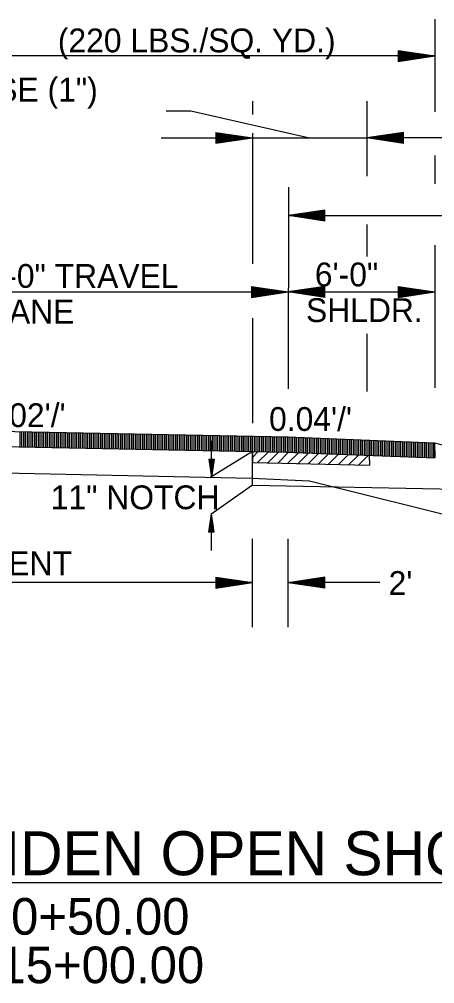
# Model space of a CAD drawing. Extents: x 1373719 to 1374161, y 379835 to 380167.
# Drawn here: x 1373788.32 to 1373799.66, y 380098.88 to 380125.22 of the extents above; entities that cross this region are included whole.
import ezdxf

# ---------------------------------------------------------------- set-up
doc = ezdxf.new("R2010")
doc.units = 0
for name, color, linetype in [('ACHM Surface', 7, 'Continuous'), ('Binder', 7, 'Continuous'), ('GREEN_TXT', 7, 'Continuous'), ('Pavement Layers', 7, 'Continuous'), ('T_Drafting', 7, 'Continuous')]:
    doc.layers.add(name, color=color, linetype=linetype)

msp = doc.modelspace()

# ---------------------------------------------------------------- linework, layer by layer
for p, q in [((1373784.662, 380114.03), (1373795.66, 380113.81)), ((1373795.66, 380113.81), (1373799.657, 380113.65)), ((1373799.657, 380113.65), (1373815.66, 380109.65)), ((1373794.689, 380112.496), (1373805.107, 380112.288))]:
    msp.add_line(p, q)
for points in [[(1373784.659, 380113.614), (1373794.689, 380113.413), (1373795.603, 380113.395), (1373797.747, 380113.31), (1373799.665, 380113.237)], [(1373794.689, 380112.496), (1373794.689, 380113.413)]]:
    msp.add_lwpolyline(points)
at = {"layer": 'ACHM Surface'}
for p, q in [((1373788.343, 380113.54), (1373788.343, 380113.957)), ((1373788.393, 380113.539), (1373788.393, 380113.956)), ((1373788.443, 380113.538), (1373788.443, 380113.955)), ((1373788.493, 380113.537), (1373788.493, 380113.954)), ((1373788.543, 380113.536), (1373788.543, 380113.953)), ((1373788.593, 380113.535), (1373788.593, 380113.952)), ((1373788.643, 380113.534), (1373788.643, 380113.951)), ((1373788.693, 380113.533), (1373788.693, 380113.95)), ((1373788.743, 380113.532), (1373788.743, 380113.949)), ((1373788.793, 380113.531), (1373788.793, 380113.948)), ((1373788.843, 380113.53), (1373788.843, 380113.947)), ((1373788.893, 380113.529), (1373788.893, 380113.946)), ((1373788.943, 380113.528), (1373788.943, 380113.945)), ((1373788.993, 380113.527), (1373788.993, 380113.944)), ((1373789.043, 380113.526), (1373789.043, 380113.943)), ((1373789.093, 380113.525), (1373789.093, 380113.942)), ((1373789.143, 380113.524), (1373789.143, 380113.941)), ((1373789.193, 380113.523), (1373789.193, 380113.94)), ((1373789.243, 380113.522), (1373789.243, 380113.939)), ((1373789.293, 380113.521), (1373789.293, 380113.938)), ((1373789.343, 380113.52), (1373789.343, 380113.937)), ((1373789.393, 380113.519), (1373789.393, 380113.936)), ((1373789.443, 380113.518), (1373789.443, 380113.935)), ((1373789.493, 380113.517), (1373789.493, 380113.934)), ((1373789.543, 380113.516), (1373789.543, 380113.933)), ((1373789.593, 380113.515), (1373789.593, 380113.932)), ((1373789.643, 380113.514), (1373789.643, 380113.931)), ((1373789.693, 380113.513), (1373789.693, 380113.93)), ((1373789.743, 380113.512), (1373789.743, 380113.929)), ((1373789.793, 380113.511), (1373789.793, 380113.928)), ((1373789.843, 380113.51), (1373789.843, 380113.927)), ((1373789.893, 380113.509), (1373789.893, 380113.926)), ((1373789.943, 380113.508), (1373789.943, 380113.925)), ((1373789.993, 380113.507), (1373789.993, 380113.924)), ((1373790.043, 380113.506), (1373790.043, 380113.923)), ((1373790.093, 380113.505), (1373790.093, 380113.922)), ((1373790.143, 380113.504), (1373790.143, 380113.921)), ((1373790.193, 380113.503), (1373790.193, 380113.92)), ((1373790.243, 380113.502), (1373790.243, 380113.919)), ((1373790.293, 380113.501), (1373790.293, 380113.918)), ((1373790.343, 380113.5), (1373790.343, 380113.917)), ((1373790.393, 380113.499), (1373790.393, 380113.916)), ((1373790.443, 380113.498), (1373790.443, 380113.915)), ((1373790.493, 380113.497), (1373790.493, 380113.914)), ((1373790.543, 380113.496), (1373790.543, 380113.913)), ((1373790.593, 380113.495), (1373790.593, 380113.912)), ((1373790.643, 380113.494), (1373790.643, 380113.911)), ((1373790.693, 380113.493), (1373790.693, 380113.91)), ((1373790.743, 380113.492), (1373790.743, 380113.909)), ((1373790.793, 380113.491), (1373790.793, 380113.908)), ((1373790.843, 380113.49), (1373790.843, 380113.907)), ((1373790.893, 380113.489), (1373790.893, 380113.906)), ((1373790.943, 380113.488), (1373790.943, 380113.905)), ((1373790.993, 380113.487), (1373790.993, 380113.904)), ((1373791.043, 380113.486), (1373791.043, 380113.903)), ((1373791.093, 380113.485), (1373791.093, 380113.902)), ((1373791.143, 380113.484), (1373791.143, 380113.901)), ((1373791.193, 380113.483), (1373791.193, 380113.9)), ((1373791.243, 380113.482), (1373791.243, 380113.899)), ((1373791.293, 380113.481), (1373791.293, 380113.898)), ((1373791.343, 380113.48), (1373791.343, 380113.897)), ((1373791.393, 380113.479), (1373791.393, 380113.896)), ((1373791.443, 380113.478), (1373791.443, 380113.895)), ((1373791.493, 380113.477), (1373791.493, 380113.894)), ((1373791.543, 380113.476), (1373791.543, 380113.893)), ((1373791.593, 380113.475), (1373791.593, 380113.892)), ((1373791.643, 380113.474), (1373791.643, 380113.891)), ((1373791.693, 380113.473), (1373791.693, 380113.89)), ((1373791.743, 380113.472), (1373791.743, 380113.889)), ((1373791.793, 380113.471), (1373791.793, 380113.888)), ((1373791.843, 380113.47), (1373791.843, 380113.887)), ((1373791.893, 380113.469), (1373791.893, 380113.886)), ((1373791.943, 380113.468), (1373791.943, 380113.885)), ((1373791.993, 380113.467), (1373791.993, 380113.884)), ((1373792.043, 380113.466), (1373792.043, 380113.883)), ((1373792.093, 380113.465), (1373792.093, 380113.882)), ((1373792.143, 380113.464), (1373792.143, 380113.881)), ((1373792.193, 380113.463), (1373792.193, 380113.88)), ((1373792.243, 380113.462), (1373792.243, 380113.879)), ((1373792.293, 380113.461), (1373792.293, 380113.878)), ((1373792.343, 380113.46), (1373792.343, 380113.877)), ((1373792.393, 380113.459), (1373792.393, 380113.876)), ((1373792.443, 380113.458), (1373792.443, 380113.875)), ((1373792.493, 380113.457), (1373792.493, 380113.874)), ((1373792.543, 380113.456), (1373792.543, 380113.873)), ((1373792.593, 380113.455), (1373792.593, 380113.872)), ((1373792.643, 380113.454), (1373792.643, 380113.871)), ((1373792.693, 380113.453), (1373792.693, 380113.87)), ((1373792.743, 380113.452), (1373792.743, 380113.869)), ((1373792.793, 380113.451), (1373792.793, 380113.868)), ((1373792.843, 380113.45), (1373792.843, 380113.867)), ((1373792.893, 380113.449), (1373792.893, 380113.866)), ((1373792.943, 380113.448), (1373792.943, 380113.865)), ((1373792.993, 380113.447), (1373792.993, 380113.864)), ((1373793.043, 380113.446), (1373793.043, 380113.863)), ((1373793.093, 380113.445), (1373793.093, 380113.862)), ((1373793.143, 380113.444), (1373793.143, 380113.861)), ((1373793.193, 380113.443), (1373793.193, 380113.86)), ((1373793.243, 380113.442), (1373793.243, 380113.859)), ((1373793.293, 380113.441), (1373793.293, 380113.858)), ((1373793.343, 380113.44), (1373793.343, 380113.857)), ((1373793.393, 380113.439), (1373793.393, 380113.856)), ((1373793.443, 380113.438), (1373793.443, 380113.855)), ((1373793.493, 380113.437), (1373793.493, 380113.854)), ((1373793.543, 380113.436), (1373793.543, 380113.853)), ((1373793.593, 380113.435), (1373793.593, 380113.852)), ((1373793.643, 380113.434), (1373793.643, 380113.851)), ((1373793.693, 380113.433), (1373793.693, 380113.85)), ((1373793.743, 380113.432), (1373793.743, 380113.849)), ((1373793.793, 380113.431), (1373793.793, 380113.848)), ((1373793.843, 380113.43), (1373793.843, 380113.847)), ((1373793.893, 380113.429), (1373793.893, 380113.846)), ((1373793.943, 380113.428), (1373793.943, 380113.845)), ((1373793.993, 380113.427), (1373793.993, 380113.844)), ((1373794.043, 380113.426), (1373794.043, 380113.843)), ((1373794.093, 380113.425), (1373794.093, 380113.842)), ((1373794.143, 380113.424), (1373794.143, 380113.841)), ((1373794.193, 380113.423), (1373794.193, 380113.84)), ((1373794.243, 380113.422), (1373794.243, 380113.839)), ((1373794.293, 380113.421), (1373794.293, 380113.838)), ((1373794.343, 380113.42), (1373794.343, 380113.837)), ((1373794.393, 380113.419), (1373794.393, 380113.836)), ((1373794.443, 380113.418), (1373794.443, 380113.835)), ((1373794.493, 380113.417), (1373794.493, 380113.834)), ((1373794.543, 380113.416), (1373794.543, 380113.833)), ((1373794.593, 380113.415), (1373794.593, 380113.832)), ((1373794.643, 380113.414), (1373794.643, 380113.831)), ((1373794.693, 380113.413), (1373794.693, 380113.83)), ((1373794.743, 380113.412), (1373794.743, 380113.829)), ((1373794.793, 380113.411), (1373794.793, 380113.828)), ((1373794.843, 380113.41), (1373794.843, 380113.827)), ((1373794.893, 380113.409), (1373794.893, 380113.826)), ((1373794.943, 380113.408), (1373794.943, 380113.825)), ((1373794.993, 380113.407), (1373794.993, 380113.824)), ((1373795.043, 380113.406), (1373795.043, 380113.823)), ((1373795.093, 380113.405), (1373795.093, 380113.822)), ((1373795.143, 380113.404), (1373795.143, 380113.821)), ((1373795.193, 380113.403), (1373795.193, 380113.82)), ((1373795.243, 380113.402), (1373795.243, 380113.819)), ((1373795.293, 380113.401), (1373795.293, 380113.818)), ((1373795.343, 380113.4), (1373795.343, 380113.817)), ((1373795.393, 380113.399), (1373795.393, 380113.816)), ((1373795.443, 380113.398), (1373795.443, 380113.815)), ((1373795.493, 380113.397), (1373795.493, 380113.814)), ((1373795.543, 380113.396), (1373795.543, 380113.813)), ((1373795.593, 380113.395), (1373795.593, 380113.812)), ((1373795.643, 380113.394), (1373795.643, 380113.811)), ((1373795.693, 380113.392), (1373795.693, 380113.809)), ((1373795.743, 380113.39), (1373795.743, 380113.807)), ((1373795.793, 380113.388), (1373795.793, 380113.805)), ((1373795.843, 380113.386), (1373795.843, 380113.803)), ((1373795.893, 380113.384), (1373795.893, 380113.801)), ((1373795.943, 380113.382), (1373795.943, 380113.799)), ((1373795.993, 380113.38), (1373795.993, 380113.797)), ((1373796.043, 380113.379), (1373796.043, 380113.795)), ((1373796.093, 380113.377), (1373796.093, 380113.793)), ((1373796.143, 380113.375), (1373796.143, 380113.791)), ((1373796.193, 380113.373), (1373796.193, 380113.789)), ((1373796.243, 380113.371), (1373796.243, 380113.787)), ((1373796.293, 380113.369), (1373796.293, 380113.785)), ((1373796.343, 380113.367), (1373796.343, 380113.783)), ((1373796.393, 380113.365), (1373796.393, 380113.781)), ((1373796.443, 380113.363), (1373796.443, 380113.779)), ((1373796.493, 380113.361), (1373796.493, 380113.777)), ((1373796.543, 380113.359), (1373796.543, 380113.775)), ((1373796.593, 380113.357), (1373796.593, 380113.773)), ((1373796.643, 380113.355), (1373796.643, 380113.771)), ((1373796.693, 380113.353), (1373796.693, 380113.769)), ((1373796.743, 380113.351), (1373796.743, 380113.767)), ((1373796.793, 380113.349), (1373796.793, 380113.765)), ((1373796.843, 380113.347), (1373796.843, 380113.763)), ((1373796.893, 380113.345), (1373796.893, 380113.761)), ((1373796.943, 380113.343), (1373796.943, 380113.759)), ((1373796.993, 380113.341), (1373796.993, 380113.757)), ((1373797.043, 380113.339), (1373797.043, 380113.755)), ((1373797.093, 380113.337), (1373797.093, 380113.753)), ((1373797.143, 380113.335), (1373797.143, 380113.751)), ((1373797.193, 380113.334), (1373797.193, 380113.749)), ((1373797.243, 380113.332), (1373797.243, 380113.747)), ((1373797.293, 380113.33), (1373797.293, 380113.745)), ((1373797.343, 380113.328), (1373797.343, 380113.743)), ((1373797.393, 380113.326), (1373797.393, 380113.741)), ((1373797.443, 380113.324), (1373797.443, 380113.739)), ((1373797.493, 380113.322), (1373797.493, 380113.737)), ((1373797.543, 380113.32), (1373797.543, 380113.735)), ((1373797.593, 380113.318), (1373797.593, 380113.733)), ((1373797.643, 380113.316), (1373797.643, 380113.731)), ((1373797.693, 380113.314), (1373797.693, 380113.729)), ((1373797.743, 380113.312), (1373797.743, 380113.727)), ((1373797.793, 380113.31), (1373797.793, 380113.725)), ((1373797.843, 380113.308), (1373797.843, 380113.723)), ((1373797.893, 380113.306), (1373797.893, 380113.721)), ((1373797.943, 380113.304), (1373797.943, 380113.719)), ((1373797.993, 380113.302), (1373797.993, 380113.717)), ((1373798.043, 380113.3), (1373798.043, 380113.715)), ((1373798.093, 380113.298), (1373798.093, 380113.713)), ((1373798.143, 380113.296), (1373798.143, 380113.711)), ((1373798.193, 380113.294), (1373798.193, 380113.709)), ((1373798.243, 380113.292), (1373798.243, 380113.707)), ((1373798.293, 380113.291), (1373798.293, 380113.705)), ((1373798.343, 380113.289), (1373798.343, 380113.703)), ((1373798.393, 380113.287), (1373798.393, 380113.701)), ((1373798.443, 380113.285), (1373798.443, 380113.699)), ((1373798.493, 380113.283), (1373798.493, 380113.697)), ((1373798.543, 380113.281), (1373798.543, 380113.695)), ((1373798.593, 380113.279), (1373798.593, 380113.693)), ((1373798.643, 380113.277), (1373798.643, 380113.691)), ((1373798.693, 380113.275), (1373798.693, 380113.689)), ((1373798.743, 380113.273), (1373798.743, 380113.687)), ((1373798.793, 380113.271), (1373798.793, 380113.685)), ((1373798.843, 380113.269), (1373798.843, 380113.683)), ((1373798.893, 380113.267), (1373798.893, 380113.681)), ((1373798.943, 380113.265), (1373798.943, 380113.679)), ((1373798.993, 380113.263), (1373798.993, 380113.677)), ((1373799.043, 380113.261), (1373799.043, 380113.675)), ((1373799.093, 380113.259), (1373799.093, 380113.673)), ((1373799.143, 380113.257), (1373799.143, 380113.671)), ((1373799.193, 380113.255), (1373799.193, 380113.669)), ((1373799.243, 380113.253), (1373799.243, 380113.667)), ((1373799.293, 380113.251), (1373799.293, 380113.665)), ((1373799.343, 380113.249), (1373799.343, 380113.663)), ((1373799.393, 380113.248), (1373799.393, 380113.661)), ((1373799.443, 380113.246), (1373799.443, 380113.659)), ((1373799.493, 380113.244), (1373799.493, 380113.657)), ((1373799.543, 380113.242), (1373799.543, 380113.655)), ((1373799.593, 380113.24), (1373799.593, 380113.653)), ((1373799.643, 380113.238), (1373799.643, 380113.651))]:
    msp.add_line(p, q, dxfattribs=at)
at = {"layer": 'Binder'}
for p, q in [((1373794.689, 380113.254), (1373794.844, 380113.41)), ((1373794.827, 380113.11), (1373795.122, 380113.404)), ((1373795.104, 380113.104), (1373795.399, 380113.399)), ((1373795.381, 380113.097), (1373795.675, 380113.392)), ((1373795.657, 380113.091), (1373795.947, 380113.381)), ((1373795.934, 380113.085), (1373796.219, 380113.371)), ((1373796.211, 380113.079), (1373796.492, 380113.36)), ((1373796.487, 380113.073), (1373796.764, 380113.349)), ((1373796.764, 380113.067), (1373797.036, 380113.338)), ((1373797.041, 380113.06), (1373797.308, 380113.327)), ((1373797.317, 380113.054), (1373797.58, 380113.317)), ((1373797.594, 380113.048), (1373797.852, 380113.306)), ((1373797.871, 380113.042), (1373797.881, 380113.052))]:
    msp.add_line(p, q, dxfattribs=at)
at = {"layer": 'GREEN_TXT'}
for p, q in [((1373799.665, 380125.217), (1373799.665, 380122.691)), ((1373799.665, 380124.217), (1373769.664, 380124.217)), ((1373798.665, 380124.367), (1373799.665, 380124.217)), ((1373798.665, 380124.367), (1373798.665, 380124.067)), ((1373798.665, 380124.342), (1373799.498, 380124.217)), ((1373798.665, 380124.317), (1373799.326, 380124.217)), ((1373798.665, 380124.292), (1373799.159, 380124.217)), ((1373798.665, 380124.266), (1373798.99, 380124.217)), ((1373798.665, 380124.241), (1373798.823, 380124.217)), ((1373798.665, 380124.067), (1373799.665, 380124.217)), ((1373798.665, 380124.168), (1373798.99, 380124.217)), ((1373798.665, 380124.118), (1373799.326, 380124.217)), ((1373798.665, 380124.092), (1373799.498, 380124.217)), ((1373798.665, 380124.143), (1373799.159, 380124.217)), ((1373798.665, 380124.194), (1373798.823, 380124.217)), ((1373794.689, 380122.98), (1373794.689, 380122.615)), ((1373797.808, 380122.98), (1373797.808, 380120.931)), ((1373793.689, 380122.13), (1373794.689, 380121.98)), ((1373793.689, 380122.13), (1373793.689, 380121.83)), ((1373793.689, 380122.105), (1373794.522, 380121.98)), ((1373794.689, 380122.11), (1373794.689, 380118.539)), ((1373798.812, 380122.128), (1373797.812, 380121.978)), ((1373798.812, 380121.828), (1373798.812, 380122.128)), ((1373792.193, 380121.98), (1373794.693, 380121.978)), ((1373793.689, 380122.08), (1373794.35, 380121.98)), ((1373793.689, 380122.055), (1373794.183, 380121.98)), ((1373793.689, 380122.029), (1373794.014, 380121.98)), ((1373793.689, 380122.004), (1373793.847, 380121.98)), ((1373793.689, 380121.83), (1373794.689, 380121.98)), ((1373793.689, 380121.931), (1373794.014, 380121.98)), ((1373793.689, 380121.881), (1373794.35, 380121.98)), ((1373793.689, 380121.855), (1373794.522, 380121.98)), ((1373793.689, 380121.906), (1373794.183, 380121.98)), ((1373793.689, 380121.957), (1373793.847, 380121.98)), ((1373794.689, 380121.98), (1373797.808, 380121.98)), ((1373800.308, 380121.98), (1373797.808, 380121.98)), ((1373798.812, 380121.828), (1373797.812, 380121.978)), ((1373798.812, 380122.103), (1373797.979, 380121.978)), ((1373798.812, 380121.853), (1373797.979, 380121.978)), ((1373798.812, 380122.077), (1373798.151, 380121.978)), ((1373798.812, 380121.878), (1373798.151, 380121.978)), ((1373798.812, 380122.052), (1373798.317, 380121.978)), ((1373798.812, 380121.903), (1373798.317, 380121.978)), ((1373798.812, 380122.027), (1373798.487, 380121.978)), ((1373798.812, 380121.929), (1373798.487, 380121.978)), ((1373798.812, 380122.001), (1373798.654, 380121.978)), ((1373798.812, 380121.954), (1373798.654, 380121.978)), ((1373799.665, 380121.501), (1373799.665, 380120.719)), ((1373795.668, 380120.628), (1373795.662, 380115.124)), ((1373796.668, 380120.005), (1373795.668, 380119.855)), ((1373796.668, 380119.705), (1373796.668, 380120.005)), ((1373795.668, 380119.855), (1373815.66, 380119.855)), ((1373796.668, 380119.705), (1373795.668, 380119.855)), ((1373796.668, 380119.98), (1373795.835, 380119.855)), ((1373796.668, 380119.73), (1373795.835, 380119.855)), ((1373796.668, 380119.954), (1373796.007, 380119.855)), ((1373796.668, 380119.755), (1373796.007, 380119.855)), ((1373796.668, 380119.929), (1373796.174, 380119.855)), ((1373796.668, 380119.78), (1373796.174, 380119.855)), ((1373796.668, 380119.904), (1373796.343, 380119.855)), ((1373796.668, 380119.806), (1373796.343, 380119.855)), ((1373796.668, 380119.878), (1373796.51, 380119.855)), ((1373796.668, 380119.831), (1373796.51, 380119.855)), ((1373797.808, 380119.609), (1373797.808, 380118.742)), ((1373799.665, 380119.048), (1373799.665, 380115.151)), ((1373794.665, 380117.922), (1373795.665, 380117.772)), ((1373794.665, 380117.922), (1373794.665, 380117.622)), ((1373794.665, 380117.897), (1373795.498, 380117.772)), ((1373796.665, 380117.922), (1373795.665, 380117.772)), ((1373796.665, 380117.897), (1373795.832, 380117.772)), ((1373796.665, 380117.622), (1373796.665, 380117.922)), ((1373798.665, 380117.922), (1373799.665, 380117.772)), ((1373798.665, 380117.922), (1373798.665, 380117.622)), ((1373798.665, 380117.897), (1373799.498, 380117.772)), ((1373773.664, 380117.772), (1373795.664, 380117.772)), ((1373794.665, 380117.871), (1373795.326, 380117.772)), ((1373794.665, 380117.846), (1373795.159, 380117.772)), ((1373794.665, 380117.82), (1373794.99, 380117.772)), ((1373794.665, 380117.795), (1373794.823, 380117.772)), ((1373794.665, 380117.622), (1373795.665, 380117.772)), ((1373794.665, 380117.723), (1373794.99, 380117.772)), ((1373794.665, 380117.672), (1373795.326, 380117.772)), ((1373794.665, 380117.647), (1373795.498, 380117.772)), ((1373794.665, 380117.697), (1373795.159, 380117.772)), ((1373794.665, 380117.748), (1373794.823, 380117.772)), ((1373795.665, 380117.772), (1373799.665, 380117.772)), ((1373796.665, 380117.622), (1373795.665, 380117.772)), ((1373796.665, 380117.647), (1373795.832, 380117.772)), ((1373796.665, 380117.871), (1373796.004, 380117.772)), ((1373796.665, 380117.672), (1373796.004, 380117.772)), ((1373796.665, 380117.846), (1373796.17, 380117.772)), ((1373796.665, 380117.697), (1373796.17, 380117.772)), ((1373796.665, 380117.821), (1373796.34, 380117.772)), ((1373796.665, 380117.723), (1373796.34, 380117.772)), ((1373796.665, 380117.795), (1373796.507, 380117.772)), ((1373796.665, 380117.748), (1373796.507, 380117.772)), ((1373798.665, 380117.871), (1373799.326, 380117.772)), ((1373798.665, 380117.846), (1373799.159, 380117.772)), ((1373798.665, 380117.82), (1373798.99, 380117.772)), ((1373798.665, 380117.795), (1373798.823, 380117.772)), ((1373798.665, 380117.622), (1373799.665, 380117.772)), ((1373798.665, 380117.723), (1373798.99, 380117.772)), ((1373798.665, 380117.672), (1373799.326, 380117.772)), ((1373798.665, 380117.647), (1373799.498, 380117.772)), ((1373798.665, 380117.697), (1373799.159, 380117.772)), ((1373798.665, 380117.748), (1373798.823, 380117.772)), ((1373794.689, 380117.055), (1373794.689, 380114.189)), ((1373797.808, 380116.625), (1373797.808, 380115.049)), ((1373793.567, 380112.708), (1373793.567, 380113.708)), ((1373794.686, 380113.414), (1373793.526, 380112.691)), ((1373793.492, 380113.208), (1373793.567, 380112.708)), ((1373793.492, 380113.208), (1373793.642, 380113.208)), ((1373793.505, 380113.208), (1373793.567, 380112.791)), ((1373793.518, 380113.208), (1373793.567, 380112.877)), ((1373793.53, 380113.208), (1373793.567, 380112.961)), ((1373793.543, 380113.208), (1373793.567, 380113.045)), ((1373793.556, 380113.208), (1373793.567, 380113.129)), ((1373793.642, 380113.208), (1373793.567, 380112.708)), ((1373793.592, 380113.208), (1373793.567, 380113.045)), ((1373793.617, 380113.208), (1373793.567, 380112.877)), ((1373793.63, 380113.208), (1373793.567, 380112.791)), ((1373793.605, 380113.208), (1373793.567, 380112.961)), ((1373793.579, 380113.208), (1373793.567, 380113.129)), ((1373794.686, 380112.497), (1373793.548, 380111.691)), ((1373793.492, 380111.21), (1373793.567, 380111.71)), ((1373793.505, 380111.21), (1373793.567, 380111.626)), ((1373793.567, 380110.71), (1373793.567, 380111.71)), ((1373793.642, 380111.21), (1373793.567, 380111.71)), ((1373793.63, 380111.21), (1373793.567, 380111.626)), ((1373793.518, 380111.21), (1373793.567, 380111.54)), ((1373793.53, 380111.21), (1373793.567, 380111.457)), ((1373793.543, 380111.21), (1373793.567, 380111.372)), ((1373793.617, 380111.21), (1373793.567, 380111.54)), ((1373793.605, 380111.21), (1373793.567, 380111.457)), ((1373793.592, 380111.21), (1373793.567, 380111.372)), ((1373793.642, 380111.21), (1373793.492, 380111.21)), ((1373793.556, 380111.21), (1373793.567, 380111.289)), ((1373793.579, 380111.21), (1373793.567, 380111.289)), ((1373794.689, 380109.832), (1373774.689, 380109.832)), ((1373793.689, 380109.982), (1373794.689, 380109.832)), ((1373793.689, 380109.982), (1373793.689, 380109.682)), ((1373793.689, 380109.957), (1373794.522, 380109.832)), ((1373793.689, 380109.932), (1373794.35, 380109.832)), ((1373793.689, 380109.907), (1373794.183, 380109.832)), ((1373793.689, 380109.881), (1373794.014, 380109.832)), ((1373793.689, 380109.856), (1373793.847, 380109.832)), ((1373793.689, 380109.682), (1373794.689, 380109.832)), ((1373793.689, 380109.783), (1373794.014, 380109.832)), ((1373793.689, 380109.733), (1373794.35, 380109.832)), ((1373793.689, 380109.707), (1373794.522, 380109.832)), ((1373793.689, 380109.758), (1373794.183, 380109.832)), ((1373793.689, 380109.809), (1373793.847, 380109.832)), ((1373798.162, 380109.832), (1373795.662, 380109.832)), ((1373796.665, 380109.98), (1373795.665, 380109.83)), ((1373796.665, 380109.68), (1373795.665, 380109.83)), ((1373796.665, 380109.955), (1373795.832, 380109.83)), ((1373796.665, 380109.705), (1373795.832, 380109.83)), ((1373796.665, 380109.93), (1373796.004, 380109.83)), ((1373796.665, 380109.731), (1373796.004, 380109.83)), ((1373796.665, 380109.905), (1373796.171, 380109.83)), ((1373796.665, 380109.756), (1373796.171, 380109.83)), ((1373796.665, 380109.879), (1373796.34, 380109.83)), ((1373796.665, 380109.782), (1373796.34, 380109.83)), ((1373796.665, 380109.854), (1373796.507, 380109.83)), ((1373796.665, 380109.807), (1373796.507, 380109.83)), ((1373796.665, 380109.68), (1373796.665, 380109.98)), ((1373759.662, 380101.641), (1373809.617, 380101.641))]:
    msp.add_line(p, q, dxfattribs=at)
for points in [[(1373792.332, 380122.715), (1373793.006, 380122.715), (1373796.248, 380121.98)], [(1373794.689, 380108.619), (1373794.689, 380111.025)], [(1373795.662, 380108.619), (1373795.662, 380111.025)]]:
    msp.add_lwpolyline(points, dxfattribs=at)
at = {"layer": 'Pavement Layers'}
for p, q in [((1373794.689, 380113.413), (1373795.657, 380113.394)), ((1373799.657, 380113.65), (1373799.665, 380113.237)), ((1373795.657, 380113.394), (1373797.747, 380113.31)), ((1373797.879, 380113.305), (1373797.881, 380113.042))]:
    msp.add_line(p, q, dxfattribs=at)
msp.add_lwpolyline([(1373794.689, 380113.413), (1373794.689, 380113.113), (1373797.881, 380113.042)], dxfattribs=at)
at = {"layer": 'T_Drafting'}
msp.add_lwpolyline([(1373727.631, 380106.564), (1373744.177, 380106.487), (1373763.094, 380108.654), (1373773.229, 380112.614), (1373774.67, 380112.615), (1373784.496, 380112.903), (1373794.672, 380112.689), (1373796.247, 380112.615), (1373805.332, 380110.353), (1373813.633, 380112.909), (1373828.561, 380113.95), (1373844.667, 380113.95)], dxfattribs=at)

# ---------------------------------------------------------------- texts
at = {"layer": 'GREEN_TXT'}
for s, height, p in [('(220 LBS./SQ. YD.)', 0.65, (1373789.373, 380124.315)), ('3\'-0" ACHM BINDER COURSE (1")', 0.65, (1373776.833, 380122.971)), ('12\'-0" TRAVEL ', 0.65, (1373786.831, 380117.883)), (' 6\'-0"', 0.65, (1373796.15, 380117.924)), ('   LANE', 0.65, (1373786.831, 380116.908)), ('SHLDR.', 0.65, (1373796.15, 380116.949)), ('20\'-0" EXISTING PAVEMENT', 0.65, (1373778.222, 380110.036)), ("2'", 0.65, (1373798.406, 380109.496)), ('HWY. 115 TWO LANE NOTCH AND WIDEN OPEN SHOULDER', 1.2, (1373759.814, 380101.841)), ('STA. 109+00.00 - STA. 110+50.00', 1, (1373772.375, 380100.218)), ('STA. 112+79.00 - STA. 115+00.00', 1, (1373772.776, 380098.893))]:
    msp.add_text(s, height=height, dxfattribs=at).set_placement(p)
for s, rotation, p in [("0.02'/'", 359.98, (1373787.32, 380114.08)), ("0.04'/'", 359.98, (1373795.141, 380113.976)), ('11" NOTCH', 0.02, (1373789.179, 380111.836))]:
    msp.add_text(s, height=0.65, rotation=rotation, dxfattribs=at).set_placement(p)

doc.saveas('drawing.dxf')
